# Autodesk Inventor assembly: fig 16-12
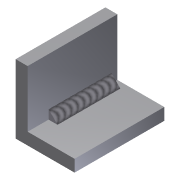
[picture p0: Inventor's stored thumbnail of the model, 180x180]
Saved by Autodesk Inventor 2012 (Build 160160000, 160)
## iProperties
Created: 2009-05
Part Number: fig 16-12
Document SubType Name: Weldment
Designer: Sham
Weld Material: Welded Aluminum-6061
Author: Sham
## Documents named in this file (2)
- C:\Users\CadCim\Documents\SAILESH\inventor-2011-fact-prt\c16-inv-2011-prt\c16_inv_2012_prt\fig 16-12.iam
- C:\Users\CadCim\Documents\SAILESH\inventor-2011-fact-prt\c16-inv-2011-prt\Part3.ipt
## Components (1 placed, 1 different names)
1. Part3:1
